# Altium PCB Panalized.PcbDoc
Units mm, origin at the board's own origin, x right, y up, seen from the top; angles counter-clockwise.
Board outline 55.5 x 72.01 mm, 2 copper layers (Top Layer, Bottom Layer), stack 1.586 mm thick; 0 components, 0 nets, 12 pads, 0 vias.
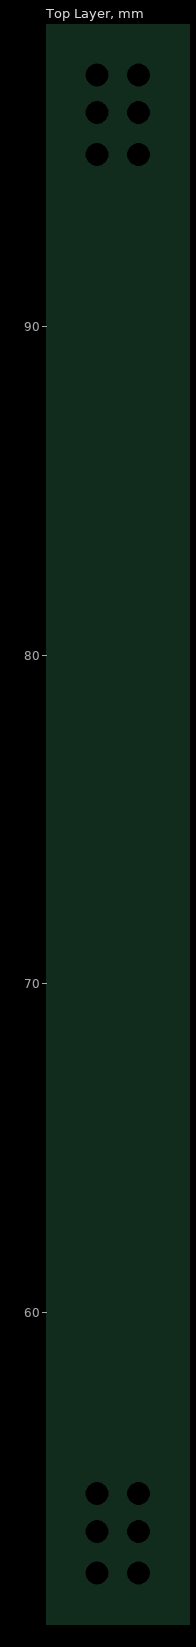
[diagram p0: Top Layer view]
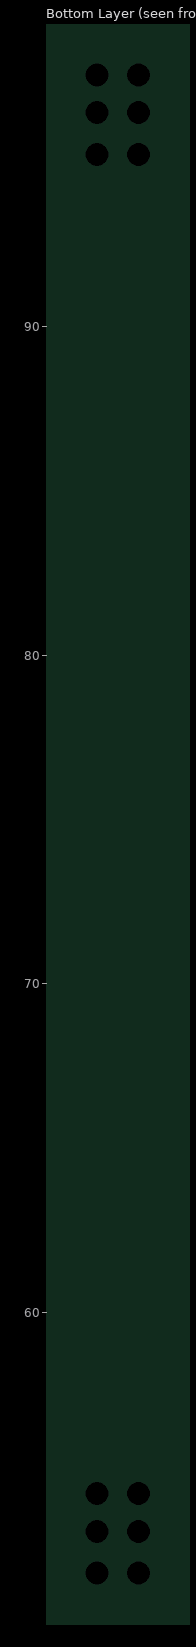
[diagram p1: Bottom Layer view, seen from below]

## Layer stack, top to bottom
Top Solder: solder mask 0.0102, Solder Resist, Dk 3.5
Top Layer: signal copper 0.018
Dielectric1: core 1.55, FR-4, Dk 4.8
Bottom Layer: signal copper 0.018
Bottom Solder: solder mask 0.0102, Solder Resist, Dk 3.5

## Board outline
62.738,39.624 62.738,111.633 118.237,111.633 118.237,39.624

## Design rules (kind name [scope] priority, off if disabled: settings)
Clearance [All] p1: gap=0.254
PolygonConnect [All] p1: connectstyle=Relief reliefconductorwidth=0.254 reliefentries=4 polygonreliefangle="90 Angle" airgapwidth=0.254
RoutingVias [All] p1: holewidth=0.711 width=1.27 viastyle="Through Hole" minholewidth=0.711 minwidth=1.27 maxholewidth=0.711 maxwidth=1.27
SolderMaskExpansion [All] p1: expansion=0.102
Width [All] p1: maxlimit=0.254 minlimit=0.254 preferedwidth=0.254
30 further rules are at their usual default settings.

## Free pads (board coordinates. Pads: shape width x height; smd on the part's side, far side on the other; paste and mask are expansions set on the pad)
  round 0 hole 0.7 unplated: 0(96.52,54.483) 0(96.52,97.663) 1(96.52,53.34) 1(96.52,96.52) 2(96.52,52.07) 2(96.52,95.25) 4(97.79,54.483) 4(97.79,97.663) 5(97.79,53.34) 5(97.79,96.52) 6(97.79,52.07) 7(97.79,95.25)

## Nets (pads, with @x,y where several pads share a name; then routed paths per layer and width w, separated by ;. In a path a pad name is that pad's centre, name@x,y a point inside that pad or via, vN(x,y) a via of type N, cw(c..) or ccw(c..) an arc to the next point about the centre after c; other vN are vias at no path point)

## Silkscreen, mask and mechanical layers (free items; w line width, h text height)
Board Outline:
  the board outline again, w0.254
Milling:
  lines w2: 97.155,39.497 97.155,50.292 ; 97.155,56.515 97.155,93.218 ; 97.155,99.441 97.155,111.76

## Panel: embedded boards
"PcbBatStack.PcbDoc" at 98.171,39.751, 1 rows x 1 columns, spacing 63.5 x 38.1, rotation 0
"PCB1.PcbDoc" at 62.738,39.751, 1 rows x 1 columns, spacing 63.5 x 38.1, rotation 0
